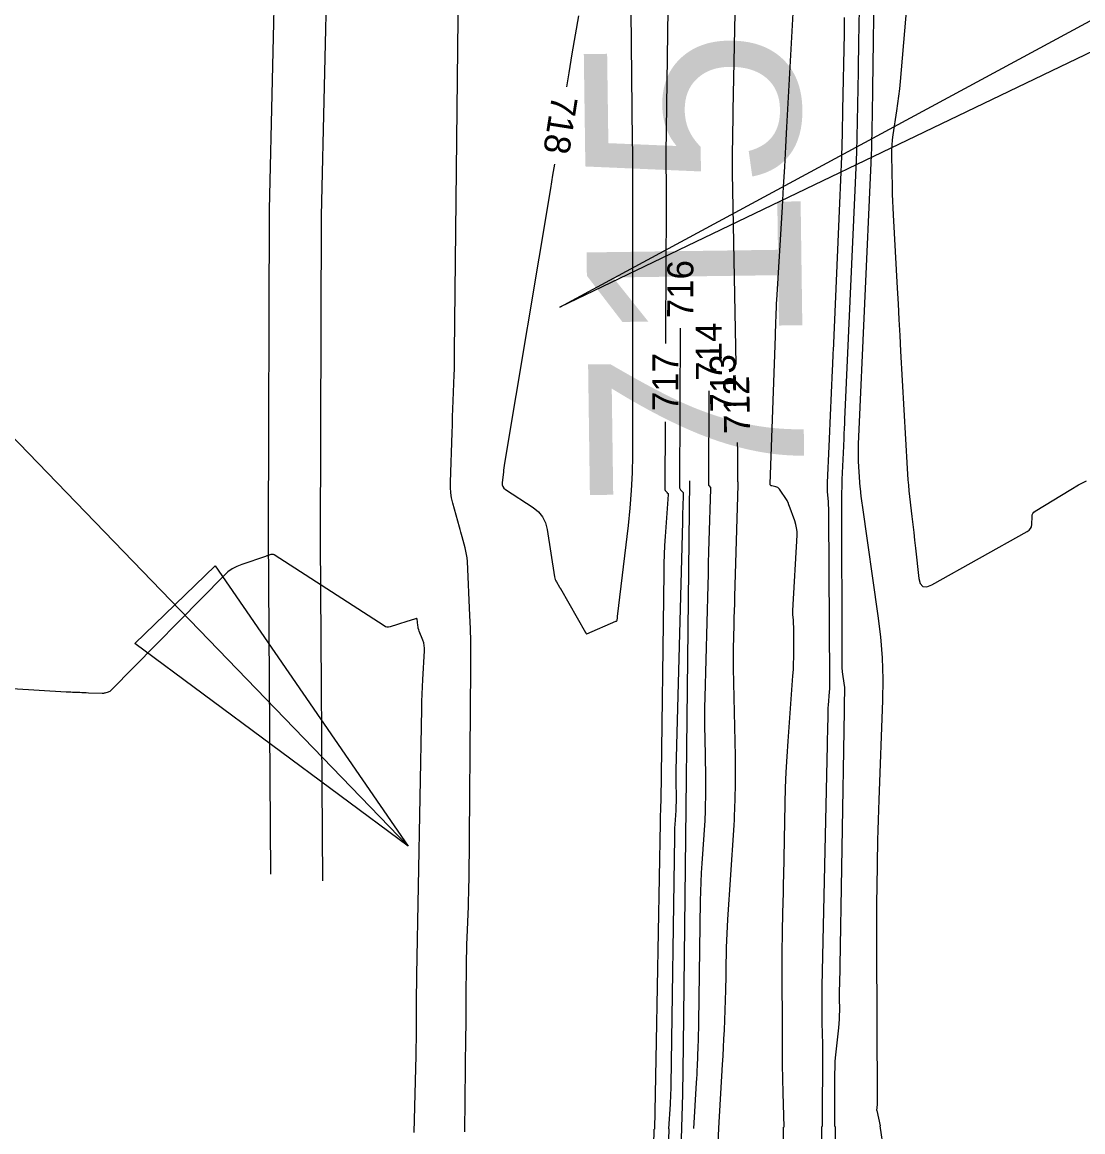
# Model space of a CAD drawing. Extents: x -361782338 to 28259792, y -263199453 to 8342113.
# Drawn here: x 1403761.5 to 1403924.5, y 576911.5 to 577082 of the extents above; entities that cross this region are included whole.
import ezdxf

# ---------------------------------------------------------------- set-up
doc = ezdxf.new("R2010")
doc.units = 0
for name, color, linetype in [('DT_X_Contour_Minor', 7, 'Continuous'), ('Level 19', 7, 'Continuous'), ('Level 40', 7, 'Continuous'), ('Level 56', 7, 'Continuous')]:
    doc.layers.add(name, color=color, linetype=linetype)

msp = doc.modelspace()

# ---------------------------------------------------------------- linework, layer by layer
at = {"layer": 'DT_X_Contour_Minor'}
msp.add_line((1403863.16, 576924.8), (1403864.12, 577011.54), dxfattribs=at)
for points in [[(1403871.56, 577108.38), (1403870.73, 577068.44), (1403870.71, 577067.48), (1403870.7, 577066.53), (1403870.68, 577065.58), (1403870.66, 577064.63), (1403870.62, 577061.52), (1403870.61, 577060.85), (1403870.61, 577060.19), (1403870.61, 577059.52), (1403870.62, 577058.86), (1403871.19, 577029.39)], [(1403892.83, 576914.79), (1403892.93, 576915.71), (1403892.95, 576915.91), (1403892.97, 576916.11), (1403892.97, 576916.31), (1403892.98, 576916.51), (1403892.85, 576940.17), (1403892.84, 576942.39), (1403892.85, 576944.61), (1403892.87, 576946.84), (1403892.9, 576949.06), (1403893.02, 576956.32), (1403893.06, 576957.87), (1403893.09, 576959.43), (1403893.14, 576960.98), (1403893.2, 576962.54), (1403893.77, 576977.8), (1403893.82, 576981.07), (1403893.72, 576984.33), (1403893.48, 576987.58), (1403893.08, 576990.82), (1403890.64, 577007.77), (1403890.59, 577008.12), (1403890.54, 577008.47), (1403890.5, 577008.83), (1403890.45, 577009.18), (1403890.32, 577010.34), (1403890.29, 577010.59), (1403890.27, 577010.84), (1403890.25, 577011.08), (1403890.24, 577011.33), (1403890.06, 577014.49), (1403890.04, 577015.16), (1403890.02, 577015.84), (1403890.03, 577016.51), (1403890.05, 577017.19), (1403891.98, 577060.41), (1403892.02, 577061.54), (1403892.06, 577062.67), (1403892.09, 577063.8), (1403892.12, 577064.93), (1403892.19, 577068.62), (1403892.2, 577069.41), (1403892.22, 577070.2), (1403892.23, 577070.99), (1403892.24, 577071.78), (1403892.75, 577108.3)], [(1403861.07, 577106.23), (1403860.42, 577061.79), (1403860.41, 577061.23), (1403860.41, 577060.68), (1403860.42, 577060.12), (1403860.42, 577059.57), (1403860.46, 577057.75), (1403860.47, 577057.36), (1403860.47, 577056.97), (1403860.47, 577056.58), (1403860.47, 577056.19), (1403860.41, 577041.44), (1403860.41, 577041.06), (1403860.41, 577040.68), (1403860.41, 577040.3), (1403860.41, 577039.92), (1403860.4, 577038.68), (1403860.4, 577038.41), (1403860.4, 577038.15), (1403860.4, 577037.88), (1403860.4, 577037.62), (1403860.39, 577036.28), (1403860.39, 577035.99), (1403860.39, 577035.7), (1403860.39, 577035.42), (1403860.39, 577035.13), (1403860.38, 577032.62)], [(1403886.38, 576912.36), (1403886.41, 576920.43), (1403886.43, 576921.4), (1403886.47, 576922.37), (1403886.54, 576923.34), (1403886.64, 576924.3), (1403887.01, 576927.52), (1403887.07, 576928.16), (1403887.11, 576928.81), (1403887.14, 576929.45), (1403887.15, 576930.1), (1403887.13, 576932.21), (1403887.13, 576932.66), (1403887.13, 576933.11), (1403887.14, 576933.57), (1403887.15, 576934.02), (1403887.87, 576976.2), (1403887.88, 576976.59), (1403887.89, 576976.98), (1403887.9, 576977.37), (1403887.91, 576977.76), (1403887.96, 576979.02), (1403887.96, 576979.3), (1403887.96, 576979.57), (1403887.94, 576979.84), (1403887.9, 576980.11), (1403887.6, 576982.2), (1403887.57, 576982.42), (1403887.55, 576982.63), (1403887.54, 576982.85), (1403887.54, 576983.07), (1403887.54, 576983.79), (1403887.54, 576983.94), (1403887.54, 576984.09), (1403887.54, 576984.25), (1403887.54, 576984.4), (1403887.5, 577008.56), (1403887.5, 577009.62), (1403887.52, 577010.67), (1403887.55, 577011.72), (1403887.59, 577012.77), (1403887.78, 577016.87), (1403887.79, 577017.27), (1403887.81, 577017.68), (1403887.83, 577018.09), (1403887.85, 577018.49), (1403887.91, 577019.82), (1403887.92, 577020.11), (1403887.94, 577020.39), (1403887.95, 577020.68), (1403887.96, 577020.96), (1403889.58, 577057.3), (1403889.68, 577059.66), (1403889.76, 577062.01), (1403889.83, 577064.37), (1403889.88, 577066.72), (1403890.02, 577074.42), (1403890.05, 577076.07), (1403890.08, 577077.72), (1403890.11, 577079.37), (1403890.13, 577081.02), (1403890.48, 577105.46)], [(1403842.21, 577004.07), (1403843.34, 576996.78), (1403843.39, 576996.58), (1403843.44, 576996.38), (1403843.52, 576996.19), (1403843.62, 576996.01), (1403844.08, 576995.21), (1403844.09, 576995.19), (1403844.11, 576995.16), (1403844.12, 576995.14), (1403844.13, 576995.11), (1403844.18, 576995.03), (1403844.19, 576995.02), (1403844.2, 576995), (1403844.21, 576994.98), (1403844.22, 576994.97), (1403848.1, 576988.24), (1403848.12, 576988.21), (1403848.13, 576988.18), (1403848.15, 576988.15), (1403848.16, 576988.12), (1403848.22, 576988.03), (1403848.23, 576988.02), (1403848.24, 576988.01), (1403848.26, 576988.01), (1403848.28, 576988.01), (1403852.77, 576989.95), (1403852.84, 576989.99), (1403852.89, 576990.04), (1403852.93, 576990.11), (1403852.95, 576990.18), (1403852.98, 576990.45), (1403852.99, 576990.51), (1403852.99, 576990.57), (1403853, 576990.63), (1403853.01, 576990.69), (1403854.68, 577004.67), (1403854.97, 577007.35), (1403855.17, 577010.04), (1403855.29, 577012.74), (1403855.34, 577015.44), (1403855.35, 577027.55), (1403855.35, 577027.8), (1403855.35, 577028.05), (1403855.35, 577028.29), (1403855.35, 577028.54), (1403855.35, 577029.36), (1403855.35, 577029.53), (1403855.35, 577029.7), (1403855.35, 577029.88), (1403855.36, 577030.05), (1403855.37, 577041.45), (1403855.37, 577043.66), (1403855.37, 577045.87), (1403855.37, 577048.08), (1403855.37, 577050.29), (1403855.36, 577057.5), (1403855.36, 577059.05), (1403855.35, 577060.59), (1403855.34, 577062.14), (1403855.33, 577063.69), (1403854.88, 577103.71)], [(1403878.59, 576912.25), (1403878.46, 576917.5), (1403878.42, 576919.65), (1403878.38, 576921.8), (1403878.36, 576923.95), (1403878.35, 576926.1), (1403878.32, 576937.25), (1403878.32, 576938.59), (1403878.33, 576939.94), (1403878.35, 576941.28), (1403878.37, 576942.63), (1403878.47, 576947.01), (1403878.49, 576947.96), (1403878.51, 576948.9), (1403878.53, 576949.84), (1403878.55, 576950.78), (1403878.77, 576961.98), (1403878.83, 576964.37), (1403878.93, 576966.77), (1403879.06, 576969.17), (1403879.22, 576971.56), (1403879.97, 576981.6), (1403880.03, 576982.53), (1403880.07, 576983.46), (1403880.1, 576984.4), (1403880.1, 576985.33), (1403880.08, 576989.22), (1403880.07, 576989.46), (1403880.07, 576989.7), (1403880.05, 576989.94), (1403880.04, 576990.18), (1403879.97, 576990.95), (1403879.96, 576991.12), (1403879.96, 576991.28), (1403879.96, 576991.45), (1403879.96, 576991.62), (1403880.59, 577003.18), (1403880.59, 577003.75), (1403880.53, 577004.3), (1403880.42, 577004.85), (1403880.25, 577005.39), (1403879.38, 577007.72), (1403879.35, 577007.8), (1403879.32, 577007.88), (1403879.29, 577007.96), (1403879.26, 577008.04), (1403879.16, 577008.3), (1403879.14, 577008.36), (1403879.12, 577008.41), (1403879.09, 577008.47), (1403879.06, 577008.52), (1403877.91, 577010.24), (1403877.8, 577010.38), (1403877.66, 577010.49), (1403877.5, 577010.58), (1403877.32, 577010.63), (1403876.71, 577010.75), (1403876.59, 577010.78), (1403876.51, 577010.85), (1403876.46, 577010.94), (1403876.45, 577011.06), (1403877.26, 577033.75), (1403877.27, 577033.9), (1403877.27, 577034.06), (1403877.28, 577034.21), (1403877.29, 577034.36), (1403877.3, 577034.87), (1403877.31, 577034.98), (1403877.31, 577035.09), (1403877.32, 577035.19), (1403877.32, 577035.3), (1403877.4, 577037.46), (1403877.41, 577037.92), (1403877.43, 577038.38), (1403877.46, 577038.84), (1403877.48, 577039.3), (1403878.34, 577053.62), (1403878.52, 577056.69), (1403878.7, 577059.76), (1403878.87, 577062.83), (1403879.04, 577065.89), (1403881.17, 577104.62)], [(1403898.9, 577101.67), (1403896.42, 577072.89), (1403896.32, 577071.75), (1403896.19, 577070.62), (1403896.05, 577069.49), (1403895.89, 577068.37), (1403895.33, 577064.69), (1403895.23, 577063.9), (1403895.16, 577063.11), (1403895.12, 577062.31), (1403895.12, 577061.52), (1403895.2, 577056.62), (1403895.23, 577055.57), (1403895.26, 577054.52), (1403895.3, 577053.47), (1403895.36, 577052.42), (1403895.98, 577041.14), (1403896.11, 577038.72), (1403896.24, 577036.3), (1403896.38, 577033.88), (1403896.51, 577031.46), (1403897.5, 577013.41), (1403897.55, 577012.56), (1403897.62, 577011.71), (1403897.7, 577010.86), (1403897.79, 577010.01)], [(1403829.56, 576911.53), (1403829.71, 576926.27), (1403829.73, 576927.77), (1403829.74, 576929.27), (1403829.75, 576930.77), (1403829.77, 576932.27), (1403829.81, 576937.17), (1403829.82, 576938.21), (1403829.84, 576939.26), (1403829.87, 576940.31), (1403829.91, 576941.36), (1403830.1, 576946.13), (1403830.13, 576947.15), (1403830.16, 576948.17), (1403830.18, 576949.19), (1403830.19, 576950.21), (1403830.49, 576982.85), (1403830.49, 576984.86), (1403830.47, 576986.86), (1403830.41, 576988.87), (1403830.33, 576990.87), (1403829.93, 576999.16), (1403829.88, 576999.69), (1403829.82, 577000.22), (1403829.72, 577000.74), (1403829.59, 577001.26), (1403829.12, 577002.95), (1403829.02, 577003.31), (1403828.92, 577003.67), (1403828.82, 577004.04), (1403828.72, 577004.4), (1403827.7, 577008.11), (1403827.51, 577008.9), (1403827.39, 577009.71), (1403827.32, 577010.52), (1403827.32, 577011.34), (1403827.59, 577018.9), (1403827.63, 577020.13), (1403827.67, 577021.36), (1403827.72, 577022.59), (1403827.76, 577023.82), (1403827.9, 577027.84), (1403827.93, 577028.7), (1403827.95, 577029.56), (1403827.97, 577030.43), (1403827.98, 577031.29), (1403828.62, 577091.93)], [(1403847.03, 577082.98), (1403846.48, 577080.07), (1403845.97, 577077.15), (1403845.5, 577074.23), (1403845.16, 577072.06)], [(1403884.48, 576912.33), (1403884.53, 576924.47), (1403884.53, 576925), (1403884.53, 576925.54), (1403884.52, 576926.07), (1403884.51, 576926.6), (1403884.47, 576928.33), (1403884.46, 576928.7), (1403884.45, 576929.07), (1403884.45, 576929.45), (1403884.45, 576929.82), (1403884.44, 576932.03), (1403884.44, 576932.5), (1403884.44, 576932.97), (1403884.45, 576933.45), (1403884.46, 576933.92), (1403885.26, 576970.94), (1403885.27, 576971.55), (1403885.28, 576972.16), (1403885.3, 576972.77), (1403885.31, 576973.38), (1403885.35, 576975.37), (1403885.36, 576975.8), (1403885.38, 576976.23), (1403885.4, 576976.65), (1403885.43, 576977.08), (1403885.58, 576979.14), (1403885.61, 576979.58), (1403885.63, 576980.03), (1403885.64, 576980.47), (1403885.64, 576980.91), (1403885.49, 577006.34), (1403885.49, 577006.83), (1403885.47, 577007.32), (1403885.44, 577007.81), (1403885.41, 577008.3), (1403885.28, 577009.89), (1403885.26, 577010.24), (1403885.25, 577010.58), (1403885.25, 577010.92), (1403885.26, 577011.27), (1403885.51, 577016.81), (1403885.56, 577017.99), (1403885.62, 577019.18), (1403885.67, 577020.37), (1403885.72, 577021.55), (1403886.04, 577028.53), (1403886.05, 577028.83), (1403886.07, 577029.12), (1403886.08, 577029.42), (1403886.09, 577029.71), (1403886.14, 577030.68), (1403886.15, 577030.89), (1403886.16, 577031.09), (1403886.16, 577031.3), (1403886.17, 577031.51), (1403887.18, 577054.2), (1403887.33, 577057.78), (1403887.46, 577061.36), (1403887.56, 577064.94), (1403887.64, 577068.52), (1403887.86, 577080.22), (1403887.91, 577082.73)], [(1403843.31, 577060.2), (1403843.03, 577058.51), (1403842.69, 577056.46), (1403835.61, 577013.96), (1403835.59, 577013.85), (1403835.57, 577013.74), (1403835.56, 577013.63), (1403835.55, 577013.52), (1403835.51, 577013.16), (1403835.5, 577013.08), (1403835.49, 577013.01), (1403835.48, 577012.93), (1403835.47, 577012.85), (1403835.29, 577011.26), (1403835.29, 577010.94), (1403835.38, 577010.66), (1403835.54, 577010.41), (1403835.79, 577010.2), (1403840.05, 577007.42), (1403840.87, 577006.76), (1403841.5, 577005.98), (1403841.95, 577005.09), (1403842.21, 577004.07)], [(1403862.62, 577034.99), (1403862.52, 577010.59), (1403862.53, 577010.47), (1403862.57, 577010.36), (1403862.62, 577010.26), (1403862.69, 577010.16), (1403863.08, 577009.74), (1403863.09, 577009.74), (1403863.09, 577009.73), (1403863.09, 577009.72), (1403863.09, 577009.71), (1403863.09, 577009.68), (1403863.09, 577009.67), (1403863.09, 577009.67), (1403863.09, 577009.66), (1403863.09, 577009.65), (1403863.02, 577007.27), (1403863.01, 577006.75), (1403862.99, 577006.24), (1403862.98, 577005.73), (1403862.97, 577005.22), (1403861.97, 576967.11), (1403861.96, 576966.6), (1403861.96, 576966.09), (1403861.96, 576965.58), (1403861.97, 576965.07), (1403862.01, 576963.14), (1403862.01, 576962.92), (1403862.01, 576962.7), (1403862.01, 576962.47), (1403862.01, 576962.25), (1403861.99, 576961.52), (1403861.99, 576961.37), (1403861.98, 576961.21), (1403861.97, 576961.06), (1403861.96, 576960.9), (1403861.81, 576958.72), (1403861.78, 576958.25), (1403861.76, 576957.78), (1403861.75, 576957.32), (1403861.74, 576956.85), (1403861.2, 576918.76), (1403861.19, 576918.47), (1403861.19, 576918.17), (1403861.18, 576917.88), (1403861.17, 576917.58), (1403861.13, 576916.61), (1403861.12, 576916.41), (1403861.11, 576916.2), (1403861.1, 576915.99), (1403861.09, 576915.79), (1403860.86, 576911.99)], [(1403867.04, 577025.38), (1403866.98, 577011.01), (1403866.99, 577010.94), (1403867.01, 577010.88), (1403867.04, 577010.82), (1403867.08, 577010.77), (1403867.25, 577010.58), (1403867.27, 577010.56), (1403867.28, 577010.53), (1403867.29, 577010.5), (1403867.29, 577010.47), (1403867.29, 577010.37), (1403867.28, 577010.35), (1403867.28, 577010.33), (1403867.28, 577010.3), (1403867.28, 577010.28), (1403867.06, 577002.32), (1403867.01, 577000.61), (1403866.96, 576998.9), (1403866.92, 576997.2), (1403866.87, 576995.49), (1403866.42, 576978.28), (1403866.39, 576976.73), (1403866.38, 576975.18), (1403866.38, 576973.63), (1403866.41, 576972.07), (1403866.53, 576966.2), (1403866.55, 576965.52), (1403866.55, 576964.84), (1403866.54, 576964.16), (1403866.53, 576963.49), (1403866.48, 576961.27), (1403866.47, 576960.8), (1403866.45, 576960.32), (1403866.42, 576959.85), (1403866.4, 576959.37), (1403865.94, 576952.73), (1403865.86, 576951.31), (1403865.79, 576949.88), (1403865.74, 576948.46), (1403865.71, 576947.03), (1403865.44, 576928.32), (1403865.43, 576927.4), (1403865.41, 576926.48), (1403865.38, 576925.56), (1403865.35, 576924.64), (1403865.24, 576921.63), (1403865.21, 576920.99), (1403865.18, 576920.35), (1403865.15, 576919.7), (1403865.11, 576919.06), (1403864.68, 576912.04)], [(1403860.33, 577020.62), (1403860.29, 577010.21), (1403860.3, 577010.15), (1403860.31, 577010.09), (1403860.34, 577010.03), (1403860.38, 577009.98), (1403860.53, 577009.83), (1403860.56, 577009.79), (1403860.59, 577009.76), (1403860.62, 577009.73), (1403860.65, 577009.69), (1403860.77, 577009.57), (1403860.79, 577009.54), (1403860.81, 577009.51), (1403860.81, 577009.47), (1403860.81, 577009.44), (1403860.34, 577002.97), (1403860.25, 577001.58), (1403860.18, 577000.2), (1403860.13, 576998.81), (1403860.1, 576997.42), (1403859.65, 576962.47), (1403859.64, 576962.13), (1403859.63, 576961.78), (1403859.63, 576961.44), (1403859.62, 576961.1), (1403859.58, 576959.98), (1403859.57, 576959.74), (1403859.57, 576959.5), (1403859.56, 576959.26), (1403859.56, 576959.02), (1403858.94, 576925.39), (1403858.84, 576920.02), (1403858.73, 576914.64), (1403858.68, 576911.96)], [(1403871.41, 577017.4), (1403871.44, 577016.17), (1403871.45, 577015.62), (1403871.45, 577015.07), (1403871.45, 577014.52), (1403871.45, 577013.97), (1403871.44, 577011.43), (1403871.45, 577011.41), (1403871.45, 577011.4), (1403871.45, 577011.39), (1403871.46, 577011.38), (1403871.49, 577011.36), (1403871.49, 577011.35), (1403871.5, 577011.34), (1403871.5, 577011.33), (1403871.5, 577011.33), (1403871.48, 577011.09), (1403871.48, 577011.04), (1403871.48, 577010.98), (1403871.48, 577010.93), (1403871.47, 577010.88), (1403870.99, 576993.75), (1403870.96, 576992.66), (1403870.93, 576991.56), (1403870.9, 576990.47), (1403870.87, 576989.37), (1403870.78, 576985.79), (1403870.76, 576985.03), (1403870.76, 576984.26), (1403870.76, 576983.49), (1403870.77, 576982.73), (1403871.06, 576969.25), (1403871.08, 576968.12), (1403871.08, 576966.99), (1403871.08, 576965.85), (1403871.06, 576964.72), (1403870.97, 576961.02), (1403870.95, 576960.22), (1403870.92, 576959.43), (1403870.88, 576958.64), (1403870.83, 576957.85), (1403869.9, 576944.14), (1403869.83, 576943.07), (1403869.78, 576941.99), (1403869.74, 576940.91), (1403869.72, 576939.83), (1403869.67, 576936.3), (1403869.65, 576935.54), (1403869.64, 576934.78), (1403869.62, 576934.03), (1403869.59, 576933.27), (1403869.37, 576927.13), (1403869.31, 576925.81), (1403869.25, 576924.49), (1403869.18, 576923.18), (1403869.11, 576921.86), (1403868.51, 576912.1)], [(1403897.79, 577010.01), (1403898.24, 577006.05), (1403898.38, 577004.83), (1403898.52, 577003.62), (1403898.65, 577002.41), (1403898.79, 577001.19), (1403899.32, 576996.55), (1403899.53, 576995.74), (1403899.93, 576995.31), (1403900.52, 576995.24), (1403901.29, 576995.54), (1403915.97, 577003.73), (1403916.25, 577003.94), (1403916.46, 577004.19), (1403916.6, 577004.49), (1403916.65, 577004.84), (1403916.71, 577006.06), (1403916.74, 577006.3), (1403916.83, 577006.51), (1403916.98, 577006.7), (1403917.17, 577006.85), (1403922.66, 577010.22), (1403923.85, 577010.91), (1403925.06, 577011.54)], [(1403821.78, 576911.42), (1403822.06, 576923.26), (1403822.09, 576924.49), (1403822.11, 576925.72), (1403822.12, 576926.95), (1403822.13, 576928.18), (1403822.14, 576932.2), (1403822.14, 576933.07), (1403822.15, 576933.93), (1403822.16, 576934.79), (1403822.17, 576935.65), (1403822.91, 576976.52), (1403822.94, 576977.65), (1403822.98, 576978.77), (1403823.03, 576979.89), (1403823.09, 576981.02), (1403823.35, 576985.41), (1403823.35, 576985.83), (1403823.31, 576986.24), (1403823.22, 576986.64), (1403823.09, 576987.04), (1403822.53, 576988.44), (1403822.46, 576988.66), (1403822.39, 576988.88), (1403822.35, 576989.1), (1403822.31, 576989.32), (1403822.2, 576990.32), (1403822.19, 576990.34), (1403822.18, 576990.36), (1403822.16, 576990.37), (1403822.13, 576990.36), (1403822.04, 576990.33), (1403822.01, 576990.33), (1403821.99, 576990.32), (1403821.97, 576990.31), (1403821.95, 576990.31), (1403820.46, 576989.85), (1403820.15, 576989.75), (1403819.83, 576989.66), (1403819.51, 576989.56), (1403819.19, 576989.46), (1403818.05, 576989.12), (1403817.81, 576989.07), (1403817.58, 576989.07), (1403817.35, 576989.13), (1403817.14, 576989.24), (1403800.24, 577000.15), (1403800.12, 577000.21), (1403800, 577000.24), (1403799.87, 577000.24), (1403799.74, 577000.21), (1403799.3, 577000.06), (1403799.21, 577000.03), (1403799.11, 577000), (1403799.02, 576999.97), (1403798.92, 576999.93), (1403795.27, 576998.7), (1403794.51, 576998.39), (1403793.8, 576998), (1403793.15, 576997.54), (1403792.54, 576996.99), (1403775.22, 576979.37), (1403775.11, 576979.27), (1403774.99, 576979.18), (1403774.85, 576979.11), (1403774.72, 576979.06), (1403774.24, 576978.91), (1403774.14, 576978.89), (1403774.04, 576978.87), (1403773.93, 576978.86), (1403773.83, 576978.86), (1403771.72, 576978.94), (1403771.38, 576978.96), (1403771.04, 576978.97), (1403770.7, 576978.98), (1403770.36, 576979), (1403769.24, 576979.04), (1403769, 576979.05), (1403768.76, 576979.06), (1403768.53, 576979.07), (1403768.29, 576979.09), (1403751.62, 576980.09)], [(1403862.2, 576889.83), (1403863.02, 576917.3), (1403863.16, 576924.8)], [(1403892.83, 576914.79), (1403893.34, 576912.46)], [(1403858.2, 576889.74), (1403858.66, 576911.96)], [(1403860.01, 576881.43), (1403860.92, 576911.99)], [(1403868.4, 576908.63), (1403868.55, 576912.1)], [(1403878.48, 576912.25), (1403878.54, 576903.78)], [(1403884.36, 576912.33), (1403884.32, 576904.28)], [(1403886.45, 576912.36), (1403886.28, 576894.22)], [(1403893.32, 576912.46), (1403893.86, 576908.67)]]:
    msp.add_lwpolyline(points, dxfattribs=at)
at = {"layer": 'Level 40'}
for p, q in [((1403778.85, 576986.54), (1403791.2, 576998.48)), ((1403791.2, 576998.48), (1403820.86, 576955.42)), ((1403820.86, 576955.42), (1403778.85, 576986.54))]:
    msp.add_line(p, q, dxfattribs=at)
msp.add_lwpolyline([(1404217.82, 577217.71), (1403844.16, 577038.22), (1404136.07, 577195.81)], close=True, dxfattribs=at)
msp.add_lwpolyline([(1403820.86, 576955.42), (1403629.75, 577153.17), (1403598.54, 577144.8)], dxfattribs=at)
at = {"layer": 'Level 56'}
for points in [[(1403799.72, 576951.13), (1403799.37, 577003.24), (1403799.52, 577053.24), (1403800.45, 577093.03), (1403801.13, 577118.22), (1403803.77, 577203.2), (1403806.32, 577303.59), (1403809.79, 577453.55), (1403811.89, 577528.32), (1403813.35, 577578.3), (1403815.32, 577653.47), (1403817.33, 577718.44), (1403820.35, 577828.2), (1403822.42, 577903.37), (1403824.98, 578003.34), (1403826.21, 578053.33), (1403828.88, 578143.09), (1403833.01, 578278.03), (1403835.33, 578353.19), (1403836.58, 578403.18), (1403837.59, 578489.24)], [(1403807.71, 576950.11), (1403807.36, 577002.22), (1403807.51, 577052.22), (1403808.43, 577092.01), (1403809.12, 577117.2), (1403811.75, 577202.18), (1403814.31, 577302.57), (1403817.77, 577452.53), (1403819.88, 577527.3), (1403821.33, 577577.28), (1403823.31, 577652.45), (1403825.32, 577717.42), (1403828.34, 577827.18), (1403830.4, 577902.36), (1403832.96, 578002.32), (1403834.2, 578052.31), (1403836.87, 578142.07), (1403841, 578277.01), (1403843.32, 578352.18), (1403844.57, 578402.16), (1403845.58, 578488.22)]]:
    msp.add_lwpolyline(points, dxfattribs=at)

# ---------------------------------------------------------------- texts
at = {"layer": 'Level 19'}
for s, height, rotation, p in [('715', 33, 90.791, (1403881.79, 577007.54)), ('718', 4, 261.1221, (1403842.96, 577070.9)), ('716', 4, 89.7902, (1403864.63, 577036.51)), ('714', 4, 90.3955, (1403869.06, 577026.93)), ('717', 4, 89.7776, (1403862.34, 577022.23)), ('713', 4, 90.7802, (1403871.26, 577022.08)), ('712', 4, 91.091, (1403873.39, 577018.79))]:
    msp.add_text(s, height=height, rotation=rotation, dxfattribs=at).set_placement(p)

doc.saveas('drawing.dxf')
